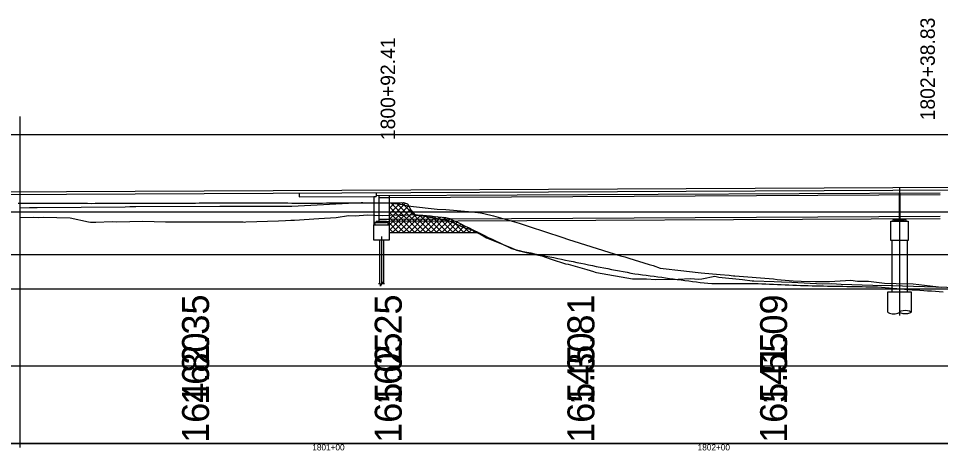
# Model space of a CAD drawing. Extents: x 2126510 to 2136144, y 865066 to 868066.
# Drawn here: x 2132622.5 to 2132861.8, y 867812.5 to 867924.5 of the extents above; entities that cross this region are included whole.
import ezdxf

# ---------------------------------------------------------------- set-up
doc = ezdxf.new("R2010")
doc.units = 0
for name, color, linetype in [('RD_DTM_BkLn1', 7, 'Continuous'), ('RD_EX_Bldg', 7, 'Continuous'), ('RD_EX_Bridge', 7, 'Continuous'), ('RD_EX_Conc_Curb', 7, 'Continuous'), ('RD_EX_DR_Pipe', 7, 'Continuous'), ('RD_EX_GuardRail', 7, 'Continuous'), ('RD_EX_H2O', 7, 'Continuous'), ('RD_EX_Misc', 7, 'Continuous'), ('RD_EX_Misc_Golf_Cartpath', 7, 'Continuous'), ('RD_EX_UT', 7, 'Continuous'), ('RD_EX_VEG', 7, 'Continuous'), ('RD_HC_Data', 7, 'Continuous'), ('RD_HC_txCode', 7, 'Continuous')]:
    doc.layers.add(name, color=color, linetype=linetype)

msp = doc.modelspace()

# ---------------------------------------------------------------- linework, layer by layer
at = {"layer": 'RD_DTM_BkLn1'}
for p, q in [((2132695.4, 867879.23), (2132695.4, 867878.23)), ((2132715.4, 867879.33), (2132715.4, 867878.33)), ((2132715.4, 867878.6), (2132861.74, 867879.33)), ((2132716.07, 867878.61), (2132716.07, 867871.9)), ((2132718.74, 867878.62), (2132718.74, 867871.03)), ((2132695.4, 867878.23), (2132715.4, 867878.33)), ((2132714.74, 867878.33), (2132714.74, 867870.9)), ((2132718.49, 867871.61), (2132714.99, 867871.61)), ((2132714.99, 867871.61), (2132714.99, 867871.03)), ((2132718.07, 867871.9), (2132715.4, 867871.9)), ((2132715.4, 867871.9), (2132715.4, 867871.61)), ((2132715.4, 867871.61), (2132718.07, 867871.61)), ((2132718.07, 867871.61), (2132718.07, 867871.9)), ((2132718.49, 867871.03), (2132718.49, 867871.61)), ((2132852.91, 867872.28), (2132849.41, 867872.28)), ((2132849.41, 867872.28), (2132849.41, 867871.95)), ((2132849.82, 867872.28), (2132852.49, 867872.28)), ((2132852.91, 867871.95), (2132852.91, 867872.28)), ((2132849.16, 867866.95), (2132849.16, 867853.64)), ((2132853.16, 867866.95), (2132853.16, 867853.64))]:
    msp.add_line(p, q, dxfattribs=at)
for points in [[(2132714.74, 867878.33), (2132715.4, 867878.33)], [(2132848.16, 867848.39), (2132848.16, 867853.64), (2132854.16, 867853.64), (2132854.16, 867848.39)]]:
    msp.add_lwpolyline(points, dxfattribs=at)
for points in [[(2132848.91, 867871.95), (2132853.41, 867871.95), (2132853.41, 867866.95), (2132848.91, 867866.95)], [(2132714.74, 867871.03), (2132718.74, 867871.03), (2132718.74, 867867.03), (2132714.74, 867867.03)]]:
    msp.add_lwpolyline(points, close=True, dxfattribs=at)
msp.add_ellipse((2132849.66, 867848.39), major_axis=(-1.5, 0), ratio=0.310397, start_param=0, end_param=3.141593, dxfattribs=at)
msp.add_ellipse((2132852.66, 867848.39), major_axis=(-1.5, 0), ratio=0.310397, dxfattribs=at)
at = {"layer": 'RD_EX_Bldg'}
for p, q in [((2132716.24, 867867.03), (2132716.24, 867855.68)), ((2132717.24, 867867.03), (2132717.24, 867855.68))]:
    msp.add_line(p, q, dxfattribs=at)
msp.add_lwpolyline([(2132717.53, 867855.68), (2132716.99, 867855.68), (2132716.99, 867856.26), (2132716.48, 867855.1), (2132716.48, 867855.68), (2132715.94, 867855.68)], dxfattribs=at)
at = {"layer": 'RD_EX_Bridge'}
for p, q in [((2132849.82, 867872.58), (2132849.82, 867872.28)), ((2132850.82, 867872.58), (2132850.82, 867872.28)), ((2132851.49, 867872.28), (2132851.49, 867872.58)), ((2132852.49, 867872.28), (2132852.49, 867872.58))]:
    msp.add_line(p, q, dxfattribs=at)
at = {"layer": 'RD_EX_Conc_Curb'}
msp.add_lwpolyline([(2132623, 867875.44), (2132625.41, 867875.46), (2132625.85, 867875.47), (2132626.97, 867875.48), (2132627.38, 867875.5), (2132650.24, 867875.69), (2132651.42, 867875.71), (2132652.01, 867875.72), (2132652.1, 867875.72), (2132652.97, 867875.73), (2132674.78, 867875.8), (2132675.46, 867875.82), (2132676.12, 867875.81), (2132692.59, 867875.85), (2132693.31, 867875.87), (2132693.39, 867875.87), (2132693.5, 867875.87), (2132711.45, 867876.76), (2132711.89, 867876.78), (2132713.1, 867876.74), (2132717.26, 867876.73), (2132719.6, 867876.62), (2132722.14, 867876.26), (2132723.61, 867875.91), (2132728.85, 867875.33), (2132731.2, 867875.06), (2132733.47, 867875.01), (2132740.3, 867874.41), (2132742.41, 867874.08), (2132743.29, 867873.95), (2132745.78, 867873.33), (2132752.44, 867871.4), (2132755.04, 867870.58), (2132763.51, 867867.81), (2132765.32, 867867.22), (2132766.65, 867866.8), (2132778.77, 867863), (2132779.9, 867862.74), (2132780.92, 867862.39), (2132786.19, 867860.71), (2132787.29, 867860.42), (2132789.08, 867859.8), (2132795.23, 867859.09), (2132795.92, 867858.97), (2132799.74, 867858.53), (2132804.64, 867858.15), (2132806.98, 867857.95), (2132807.48, 867857.87), (2132808.07, 867857.81), (2132808.4, 867857.81), (2132818.51, 867856.97), (2132819.41, 867856.81), (2132823.6, 867856.49), (2132825.65, 867856.38), (2132829.41, 867856.31), (2132832.98, 867856.29), (2132838.54, 867856.69), (2132840.3, 867856.38), (2132843.13, 867856.4), (2132847.26, 867855.88), (2132850.33, 867855.81), (2132854.68, 867855.74), (2132862.03, 867854.85)], dxfattribs=at)
at = {"layer": 'RD_EX_DR_Pipe'}
for p, q in [((2132718.74, 867873.78), (2132721.7, 867876.74)), ((2132718.74, 867875.19), (2132720.25, 867876.7)), ((2132718.74, 867876.6), (2132718.82, 867876.69)), ((2132718.74, 867872.36), (2132722.96, 867876.58)), ((2132719.19, 867876.69), (2132726.84, 867869.03)), ((2132720.58, 867876.71), (2132728.26, 867869.03)), ((2132721.96, 867876.75), (2132729.67, 867869.03)), ((2132718.74, 867870.95), (2132723.74, 867875.95)), ((2132718.74, 867875.73), (2132725.43, 867869.03)), ((2132718.74, 867869.53), (2132724.27, 867875.06)), ((2132718.74, 867874.31), (2132724.02, 867869.03)), ((2132719.65, 867869.03), (2132724.86, 867874.24)), ((2132718.74, 867872.9), (2132722.6, 867869.03)), ((2132718.74, 867871.48), (2132721.19, 867869.03)), ((2132721.07, 867869.03), (2132725.52, 867873.49)), ((2132722.48, 867869.03), (2132726.93, 867873.48)), ((2132723.9, 867869.03), (2132728.29, 867873.43)), ((2132725.31, 867869.03), (2132729.57, 867873.3)), ((2132726.64, 867873.48), (2132731.09, 867869.03)), ((2132726.72, 867869.03), (2132730.85, 867873.16)), ((2132728.1, 867873.44), (2132732.5, 867869.03)), ((2132728.14, 867869.03), (2132732.13, 867873.02)), ((2132729.55, 867869.03), (2132733.4, 867872.89)), ((2132729.66, 867873.29), (2132733.92, 867869.03)), ((2132730.97, 867869.03), (2132734.53, 867872.59)), ((2132731.25, 867873.12), (2132735.33, 867869.03)), ((2132732.38, 867869.03), (2132735.48, 867872.13)), ((2132732.83, 867872.95), (2132736.74, 867869.03)), ((2132733.79, 867869.03), (2132736.43, 867871.67)), ((2132734.67, 867872.53), (2132738.16, 867869.03)), ((2132718.74, 867870.07), (2132719.77, 867869.03)), ((2132735.21, 867869.03), (2132737.38, 867871.2)), ((2132736.62, 867869.03), (2132738.33, 867870.74)), ((2132737.43, 867871.18), (2132739.57, 867869.03)), ((2132738.04, 867869.03), (2132739.28, 867870.28)), ((2132739.45, 867869.03), (2132740.23, 867869.81)), ((2132740.19, 867869.83), (2132740.99, 867869.03)), ((2132740.87, 867869.03), (2132741.18, 867869.35)), ((2132741.82, 867869.03), (2132741.47, 867869.21))]:
    msp.add_line(p, q, dxfattribs=at)
at = {"layer": 'RD_EX_GuardRail'}
for p, q in [((2135251.98, 867894.32), (2130671.73, 867894.32)), ((2133154.24, 867874.32), (2130671.73, 867874.32)), ((2135251.98, 867854.32), (2130671.73, 867854.32)), ((2135251.98, 867834.32), (2130671.73, 867834.32)), ((2135251.98, 867814.32), (2130671.73, 867814.32))]:
    msp.add_line(p, q, dxfattribs=at)
at = {"layer": 'RD_EX_H2O'}
for points in [[(2132622.47, 867876.64), (2132623.47, 867876.64), (2132624.47, 867876.64), (2132625.47, 867876.64), (2132626.47, 867876.64), (2132627.47, 867876.64), (2132628.47, 867876.64), (2132629.47, 867876.64), (2132630.47, 867876.64), (2132631.47, 867876.64), (2132632.47, 867876.63), (2132633.47, 867876.62), (2132634.47, 867876.62), (2132635.47, 867876.61), (2132636.47, 867876.61), (2132637.47, 867876.6), (2132638.47, 867876.59), (2132639.47, 867876.59), (2132640.47, 867876.58), (2132641.47, 867876.57), (2132642.47, 867876.58), (2132643.47, 867876.58), (2132644.47, 867876.59), (2132645.47, 867876.59), (2132646.47, 867876.59), (2132647.47, 867876.6), (2132648.47, 867876.6), (2132649.47, 867876.61), (2132650.47, 867876.61), (2132651.47, 867876.61), (2132652.47, 867876.62), (2132653.47, 867876.62), (2132654.47, 867876.62), (2132655.47, 867876.63), (2132656.47, 867876.63), (2132657.47, 867876.63), (2132658.47, 867876.63), (2132659.47, 867876.64), (2132660.47, 867876.64), (2132661.47, 867876.64), (2132662.47, 867876.65), (2132663.47, 867876.65), (2132664.47, 867876.65), (2132665.47, 867876.65), (2132666.47, 867876.65), (2132667.47, 867876.65), (2132668.47, 867876.65), (2132669.47, 867876.66), (2132670.47, 867876.66), (2132671.47, 867876.66), (2132672.47, 867876.66), (2132673.47, 867876.66), (2132674.47, 867876.66), (2132675.47, 867876.66), (2132676.47, 867876.67), (2132677.47, 867876.67), (2132678.47, 867876.67), (2132679.47, 867876.67), (2132680.47, 867876.67), (2132681.47, 867876.67), (2132682.47, 867876.67), (2132683.47, 867876.67), (2132684.47, 867876.67), (2132685.47, 867876.67), (2132686.47, 867876.67), (2132687.47, 867876.67), (2132688.47, 867876.66), (2132689.47, 867876.66), (2132690.47, 867876.66), (2132691.47, 867876.66)], [(2132691.47, 867876.66), (2132692.47, 867876.66), (2132693.47, 867876.65), (2132694.47, 867876.65), (2132695.47, 867876.65), (2132696.47, 867876.65), (2132697.47, 867876.64), (2132698.47, 867876.65), (2132699.47, 867876.65), (2132700.47, 867876.65), (2132701.47, 867876.65), (2132702.47, 867876.66), (2132703.47, 867876.66), (2132704.47, 867876.66), (2132705.47, 867876.67), (2132706.47, 867876.67), (2132707.47, 867876.67), (2132708.47, 867876.67), (2132709.47, 867876.67), (2132710.47, 867876.68), (2132711.47, 867876.68), (2132712.47, 867876.68), (2132713.47, 867876.68), (2132714.47, 867876.68), (2132715.47, 867876.68), (2132716.47, 867876.69), (2132717.47, 867876.69), (2132718.47, 867876.69), (2132719.47, 867876.69), (2132720.47, 867876.71), (2132721.47, 867876.73), (2132722.47, 867876.76), (2132723.47, 867876.4), (2132724.47, 867874.73), (2132725.47, 867873.49), (2132726.47, 867873.48), (2132727.47, 867873.48), (2132728.47, 867873.41), (2132729.47, 867873.31), (2132730.47, 867873.2), (2132731.47, 867873.09), (2132732.47, 867872.99), (2132733.47, 867872.88), (2132734.47, 867872.62), (2132735.47, 867872.14), (2132736.47, 867871.65), (2132737.47, 867871.16), (2132738.47, 867870.67), (2132739.47, 867870.19), (2132740.47, 867869.7), (2132741.47, 867869.21), (2132742.47, 867868.72), (2132743.47, 867868.23), (2132744.47, 867867.74), (2132745.47, 867867.26), (2132746.47, 867866.79), (2132747.47, 867866.31), (2132748.47, 867865.84), (2132749.47, 867865.37), (2132750.47, 867864.89), (2132751.47, 867864.57), (2132752.47, 867864.32), (2132753.47, 867864.11), (2132754.47, 867863.91), (2132755.47, 867863.72), (2132756.47, 867863.52), (2132757.47, 867863.31), (2132758.47, 867863.11), (2132759.47, 867862.9), (2132760.47, 867862.7), (2132761.47, 867862.49), (2132762.47, 867862.29), (2132763.47, 867862.08), (2132764.47, 867861.88), (2132765.47, 867861.67), (2132766.47, 867861.47), (2132767.47, 867861.26), (2132768.47, 867861.06), (2132769.47, 867860.85), (2132770.47, 867860.64), (2132771.47, 867860.44), (2132772.47, 867860.23), (2132773.47, 867860.03), (2132774.47, 867859.84), (2132775.47, 867859.65), (2132776.47, 867859.46), (2132777.47, 867859.27), (2132778.47, 867859.07), (2132779.47, 867858.88), (2132780.47, 867858.69), (2132781.47, 867858.5), (2132782.47, 867858.33), (2132783.47, 867858.2), (2132784.47, 867858.06), (2132785.47, 867857.93), (2132786.47, 867857.8), (2132787.47, 867857.66), (2132788.47, 867857.53), (2132789.47, 867857.4), (2132790.47, 867857.26), (2132791.47, 867857.13)], [(2132791.47, 867857.13), (2132792.47, 867857), (2132793.47, 867856.86), (2132794.47, 867856.73), (2132795.47, 867856.59), (2132796.47, 867856.46), (2132797.47, 867856.33), (2132798.47, 867856.19), (2132799.47, 867856.06), (2132800.47, 867855.96), (2132801.47, 867855.88), (2132802.47, 867855.79), (2132803.47, 867855.79), (2132804.47, 867855.8), (2132805.47, 867855.8), (2132806.47, 867855.81), (2132807.47, 867855.81), (2132808.47, 867855.82), (2132809.47, 867855.82), (2132810.47, 867855.83), (2132811.47, 867855.83), (2132812.47, 867855.82), (2132813.47, 867855.81), (2132814.47, 867855.8), (2132815.47, 867855.73), (2132816.47, 867855.67), (2132817.47, 867855.62), (2132818.47, 867855.58), (2132819.47, 867855.53), (2132820.47, 867855.49), (2132821.47, 867855.44), (2132822.47, 867855.42), (2132823.47, 867855.39), (2132824.47, 867855.34), (2132825.47, 867855.29), (2132826.47, 867855.25), (2132827.47, 867855.23), (2132828.47, 867855.21), (2132829.47, 867855.19), (2132830.47, 867855.17), (2132831.47, 867855.16), (2132832.47, 867855.14), (2132833.47, 867855.12), (2132834.47, 867855.1), (2132835.47, 867855.09), (2132836.47, 867855.07), (2132837.47, 867855.05), (2132838.47, 867855.03), (2132839.47, 867855.02), (2132840.47, 867855), (2132841.47, 867854.98), (2132842.47, 867854.96), (2132843.47, 867854.95), (2132844.47, 867854.93), (2132845.47, 867854.91), (2132846.47, 867854.83), (2132847.47, 867854.74), (2132848.47, 867854.65), (2132849.47, 867854.56), (2132850.47, 867854.48), (2132851.47, 867854.39), (2132852.47, 867854.32), (2132853.47, 867854.25), (2132854.47, 867854.18), (2132855.47, 867854.12), (2132856.47, 867854.05), (2132857.47, 867853.98), (2132858.47, 867853.92), (2132859.47, 867853.85), (2132860.47, 867853.78), (2132861.47, 867853.72), (2132862.47, 867853.65)]]:
    msp.add_lwpolyline(points, dxfattribs=at)
at = {"layer": 'RD_EX_Misc'}
for p, q in [((2132623, 867813.32), (2132623, 867899.05)), ((2132116.01, 867877.03), (2133296.65, 867882.93)), ((2131523, 867814.32), (2135677.25, 867814.32))]:
    msp.add_line(p, q, dxfattribs=at)
msp.add_lwpolyline([(2131430.13, 867814.32), (2131430.13, 867863.32), (2136143.96, 867863.32)], dxfattribs=at)
at = {"layer": 'RD_EX_Misc_Golf_Cartpath'}
msp.add_lwpolyline([(2132623, 867872.9), (2132626.34, 867873.01), (2132627.66, 867872.94), (2132629.04, 867872.99), (2132636.01, 867872.82), (2132640.76, 867871.76), (2132641.22, 867871.67), (2132642.66, 867871.65), (2132646.88, 867871.84), (2132648.08, 867871.79), (2132654.78, 867871.98), (2132660.72, 867871.76), (2132668.62, 867871.81), (2132668.68, 867871.81), (2132668.71, 867871.81), (2132668.75, 867871.81), (2132678.76, 867871.75), (2132680.83, 867871.74), (2132681.18, 867871.73), (2132681.21, 867871.73), (2132681.53, 867871.74), (2132690.02, 867872), (2132691.8, 867872.08), (2132693.21, 867872.25), (2132694.21, 867872.17), (2132700.49, 867872.64), (2132704.99, 867872.88), (2132708.23, 867873.38), (2132709.92, 867873.32), (2132713.09, 867873.63), (2132716.92, 867873.42), (2132721.15, 867873.55), (2132721.58, 867873.51), (2132722.25, 867873.53), (2132724.37, 867873.57), (2132725.61, 867873.71), (2132733.71, 867872.21), (2132734.49, 867871.98), (2132734.9, 867871.78), (2132738.28, 867870.23), (2132740.02, 867869.76), (2132743.16, 867868.15), (2132744.02, 867867.66), (2132750.48, 867865.02), (2132751.81, 867864.4), (2132755.74, 867863.48), (2132758.34, 867862.93), (2132760.77, 867862.14), (2132764.46, 867860.87), (2132765.15, 867860.84), (2132770.06, 867859.4), (2132771.73, 867858.91), (2132772.2, 867858.75), (2132772.51, 867858.68), (2132781.88, 867856.96), (2132785.52, 867856.96), (2132787.82, 867856.81), (2132793.73, 867856.93), (2132796.95, 867857.12), (2132797.94, 867856.99), (2132799.13, 867856.89), (2132799.9, 867857.02), (2132803.23, 867857.7), (2132804.32, 867857.46), (2132810.47, 867856.81), (2132812.9, 867856.46), (2132813.38, 867856.45), (2132818.61, 867856.29), (2132820.51, 867856.24), (2132823.2, 867856.11), (2132831.19, 867855.7), (2132833.61, 867855.76), (2132836.06, 867855.65), (2132844.22, 867855.36), (2132849.46, 867855.29), (2132851.98, 867855.17), (2132866.34, 867854.75)], dxfattribs=at)
at = {"layer": 'RD_EX_UT'}
msp.add_line((2132116.01, 867876.33), (2133296.65, 867882.24), dxfattribs=at)
at = {"layer": 'RD_EX_VEG'}
msp.add_line((2132718.74, 867869.03), (2132741.92, 867869.03), dxfattribs=at)
at = {"layer": 'RD_HC_Data'}
for p, q in [((2132851.16, 867880.71), (2132851.16, 867847.51)), ((2132716.74, 867867.96), (2132716.74, 867855.68))]:
    msp.add_line(p, q, dxfattribs=at)
at = {"layer": 'RD_HC_txCode'}
for p, q in [((2132718.74, 867878.12), (2132861.74, 867878.84)), ((2132851.07, 867879.28), (2132851.07, 867872.57)), ((2132851.24, 867879.28), (2132851.24, 867872.58)), ((2132716.07, 867878.11), (2132718.74, 867878.12)), ((2132716.07, 867872.48), (2132718.74, 867872.5)), ((2132716.07, 867871.9), (2132718.74, 867871.91)), ((2132718.74, 867872.5), (2132861.74, 867873.21)), ((2132718.74, 867871.91), (2132861.74, 867872.63))]:
    msp.add_line(p, q, dxfattribs=at)

# ---------------------------------------------------------------- texts
at = {"layer": 'RD_EX_Misc'}
for s, height, p in [('1802+38.83', 3.75, (2132860.34, 867898.08)), ('1800+92.41', 3.75, (2132720.29, 867892.95)), ('162.35', 7, (2132672, 867824.32)), ('162.25', 7, (2132722, 867824.32)), ('145.81', 7, (2132772, 867824.32)), ('141.09', 7, (2132822, 867824.32)), ('164.80', 7, (2132672, 867814.47)), ('165.05', 7, (2132722, 867814.47)), ('165.30', 7, (2132772, 867814.47)), ('165.55', 7, (2132822, 867814.47))]:
    msp.add_text(s, height=height, rotation=90, dxfattribs=at).set_placement(p)
for s, p in [('1801+00', (2132698.79, 867812.52)), ('1802+00', (2132798.79, 867812.52))]:
    msp.add_text(s, height=1.6, dxfattribs=at).set_placement(p)

doc.saveas('drawing.dxf')
